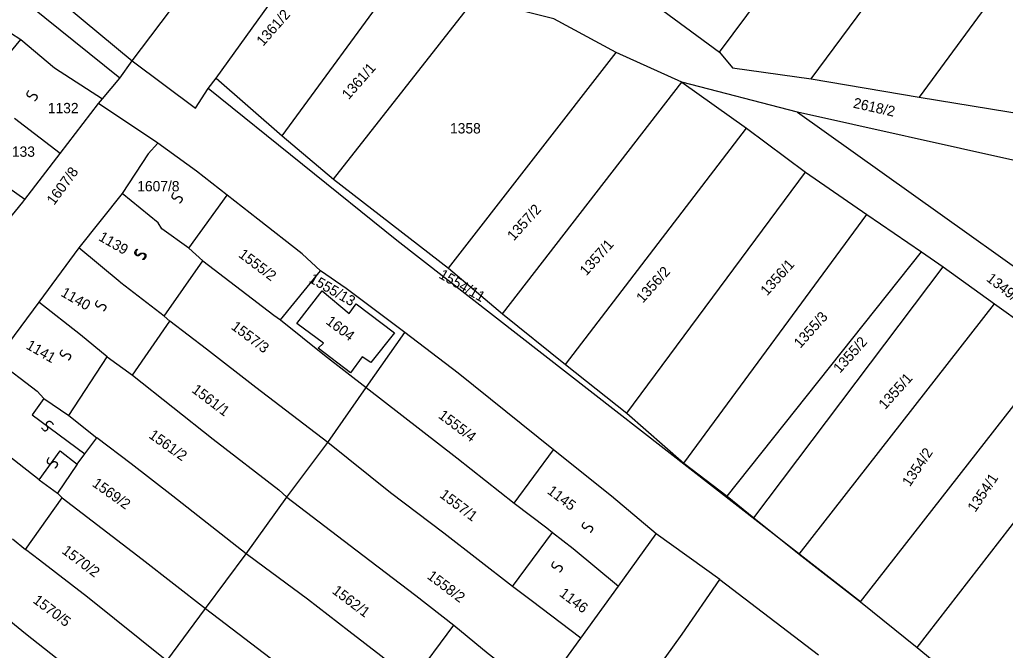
# Model space of a CAD drawing. Extents: x -581999 to -572728, y -1219553 to -1212032.
# Drawn here: x -578122.3 to -577931.4, y -1215494.4 to -1215372.3 of the extents above; entities that cross this region are included whole.
import ezdxf

# ---------------------------------------------------------------- set-up
doc = ezdxf.new("R2010")
doc.units = 0
for name, color, linetype in [('Vrstva 1', 7, 'Continuous'), ('Vrstva 2', 7, 'Continuous'), ('Vrstva 4', 7, 'Continuous'), ('Vrstva 6', 7, 'Continuous')]:
    doc.layers.add(name, color=color, linetype=linetype)

msp = doc.modelspace()

# ---------------------------------------------------------------- linework, layer by layer
at = {"layer": 'Vrstva 1'}
for p, q in [((-578100.494, -1215380.216), (-578082.103, -1215355.694)), ((-578102.918, -1215383.605), (-578100.494, -1215380.216)), ((-578049.251, -1215415.042), (-578085.815, -1215385.599)), ((-578095.516, -1215396.142), (-578107.03, -1215388.485)), ((-577959.465, -1215484.976), (-578049.251, -1215415.042)), ((-577985.234, -1215464.553), (-577947.602, -1215417.208)), ((-578071.787, -1215430.39), (-578064.022, -1215420.865)), ((-578068.651, -1215431.09), (-578063.723, -1215424.787)), ((-578063.723, -1215424.787), (-578058.496, -1215429.129)), ((-578058.496, -1215429.129), (-578057.152, -1215427.308)), ((-578057.152, -1215427.308), (-578049.686, -1215432.911)), ((-578063.424, -1215434.872), (-578068.651, -1215431.09)), ((-578049.686, -1215432.911), (-578054.315, -1215438.654)), ((-578064.47, -1215435.853), (-578063.424, -1215434.872)), ((-578058.198, -1215440.615), (-578064.47, -1215435.853)), ((-578055.958, -1215437.534), (-578058.198, -1215440.615)), ((-578054.315, -1215438.654), (-578055.958, -1215437.534)), ((-578109.693, -1215456.33), (-578107.389, -1215453.247)), ((-578111.141, -1215458.339), (-578109.693, -1215456.33)), ((-578111.141, -1215458.339), (-578114.975, -1215463.945)), ((-577986.65, -1215480.681), (-577999.043, -1215471.831))]:
    msp.add_line(p, q, dxfattribs=at)
for points in [[(-577986.724, -1215378.56), (-577942.318, -1215318.916)], [(-577968.996, -1215383.692), (-577928.473, -1215329.085)], [(-577913.954, -1215340.861), (-577948.085, -1215387.231)], [(-578106.235, -1215387.571), (-578102.918, -1215383.605), (-578123.359, -1215367.058), (-578149.788, -1215343.598)], [(-578084.26, -1215383.594), (-578067.156, -1215359.754)], [(-578071.462, -1215394.749), (-578048.947, -1215363.96)], [(-578061.488, -1215403.132), (-578034.144, -1215368.201)], [(-578006.788, -1215378.578), (-578018.826, -1215372.095), (-578034.144, -1215368.201)], [(-578113.459, -1215369.532), (-578100.494, -1215380.216), (-578088.259, -1215389.387), (-578085.815, -1215385.599), (-578084.26, -1215383.594)], [(-577999.894, -1215368.859), (-577986.724, -1215378.56)], [(-578126.151, -1215373.535), (-578122.078, -1215376.082), (-578115.59, -1215381.551)], [(-578039.247, -1215420.343), (-578006.788, -1215378.578)], [(-577994.062, -1215384.369), (-578006.788, -1215378.578)], [(-577986.724, -1215378.56), (-577984.229, -1215381.554), (-577968.996, -1215383.692)], [(-578115.59, -1215381.551), (-578106.235, -1215387.571)], [(-578084.26, -1215383.594), (-578071.462, -1215394.749)], [(-577968.996, -1215383.692), (-577948.085, -1215387.231)], [(-578028.764, -1215429.244), (-577994.062, -1215384.369)], [(-577994.062, -1215384.369), (-577981.543, -1215393.259)], [(-577971.667, -1215390.161), (-577994.062, -1215384.369)], [(-578114.476, -1215398.189), (-578107.03, -1215388.485), (-578106.235, -1215387.571)], [(-577948.085, -1215387.231), (-577923.973, -1215391.226)], [(-578114.476, -1215398.189), (-578123.285, -1215391.413)], [(-577929.364, -1215399.559), (-577971.667, -1215390.161)], [(-577971.667, -1215390.161), (-577899.516, -1215441.527), (-577893.856, -1215445.25), (-577891.34, -1215447.533), (-577869.986, -1215463.212), (-577837.934, -1215488.834)], [(-578016.564, -1215439.019), (-577981.543, -1215393.259)], [(-577981.543, -1215393.259), (-577970.066, -1215401.751)], [(-578071.462, -1215394.749), (-578061.488, -1215403.132)], [(-578088.076, -1215401.586), (-578095.516, -1215396.142), (-578097.388, -1215398.256), (-578102.479, -1215405.913)], [(-578121.289, -1215407.105), (-578114.476, -1215398.189)], [(-578121.289, -1215407.105), (-578131.743, -1215399.738)], [(-578082.13, -1215406.246), (-578088.076, -1215401.586)], [(-578004.709, -1215448.444), (-577970.066, -1215401.751)], [(-577970.066, -1215401.751), (-577958.214, -1215409.964)], [(-578061.488, -1215403.132), (-578039.247, -1215420.343)], [(-578102.479, -1215405.913), (-578110.868, -1215416.452)], [(-578095.49, -1215411.569), (-578102.479, -1215405.913)], [(-578089.544, -1215416.492), (-578082.13, -1215406.246)], [(-578047.716, -1215432.833), (-578059.067, -1215424.308), (-578064.022, -1215420.865), (-578067.607, -1215417.628), (-578076.184, -1215410.907), (-578082.13, -1215406.246)], [(-578130.278, -1215418.04), (-578121.724, -1215407.591), (-578121.289, -1215407.105)], [(-577993.632, -1215458.113), (-577958.214, -1215409.964)], [(-577958.214, -1215409.964), (-577947.602, -1215417.208), (-577943.445, -1215420.099)], [(-578094.799, -1215412.739), (-578095.49, -1215411.569)], [(-578089.544, -1215416.492), (-578094.799, -1215412.739)], [(-578110.868, -1215416.452), (-578118.619, -1215426.931)], [(-578102.732, -1215423.189), (-578102.833, -1215423.111), (-578110.868, -1215416.452)], [(-578086.832, -1215418.951), (-578089.544, -1215416.492)], [(-578094.346, -1215429.676), (-578086.832, -1215418.951)], [(-578086.832, -1215418.951), (-578073.043, -1215429.484), (-578071.787, -1215430.39), (-578063.233, -1215437.218), (-578055.191, -1215443.51)], [(-577980.066, -1215468.755), (-577943.445, -1215420.099)], [(-577943.445, -1215420.099), (-577933.487, -1215427.258)], [(-578039.247, -1215420.343), (-578028.764, -1215429.244)], [(-578094.346, -1215429.676), (-578102.732, -1215423.189)], [(-578118.619, -1215426.931), (-578126.909, -1215438.14)], [(-578110.534, -1215433.307), (-578118.619, -1215426.931)], [(-577971.31, -1215475.732), (-577933.487, -1215427.258)], [(-577933.487, -1215427.258), (-577921.22, -1215436.083)], [(-578093.249, -1215430.613), (-578094.346, -1215429.676)], [(-578028.764, -1215429.244), (-578016.564, -1215439.019)], [(-578100.437, -1215441.069), (-578093.249, -1215430.613)], [(-578062.593, -1215454.111), (-578076.594, -1215443.465), (-578086.118, -1215436.084), (-578093.249, -1215430.613)], [(-578105.338, -1215437.525), (-578110.534, -1215433.307)], [(-578055.191, -1215443.51), (-578047.716, -1215432.833)], [(-578018.91, -1215455.531), (-578037.389, -1215440.741), (-578047.716, -1215432.833)], [(-577959.465, -1215484.976), (-577921.22, -1215436.083)], [(-578126.909, -1215438.14), (-578118.938, -1215444.224)], [(-578112.759, -1215448.912), (-578105.338, -1215437.525)], [(-578105.338, -1215437.525), (-578100.437, -1215441.069)], [(-578016.564, -1215439.019), (-578004.709, -1215448.444)], [(-578100.437, -1215441.069), (-578084.807, -1215453.464), (-578072.081, -1215463.279), (-578070.581, -1215464.742)], [(-578118.938, -1215444.224), (-578117.638, -1215445.603)], [(-578062.593, -1215454.111), (-578055.191, -1215443.51)], [(-578055.191, -1215443.51), (-578037.596, -1215457.098), (-578026.496, -1215465.858)], [(-577948.48, -1215493.866), (-577910.411, -1215444.805)], [(-578117.638, -1215445.603), (-578112.759, -1215448.912)], [(-578004.709, -1215448.444), (-577993.632, -1215458.113)], [(-578112.759, -1215448.912), (-578107.389, -1215453.247)], [(-578078.452, -1215475.678), (-578092.632, -1215464.558), (-578100.714, -1215458.291), (-578107.389, -1215453.247)], [(-578070.581, -1215464.742), (-578062.593, -1215454.111)], [(-578026.822, -1215482.008), (-578040.119, -1215471.716), (-578050.479, -1215463.888), (-578062.593, -1215454.111)], [(-578118.555, -1215461.367), (-578126.341, -1215455.3), (-578126.485, -1215455.096)], [(-578026.496, -1215465.858), (-578018.91, -1215455.531)], [(-578007.667, -1215464.546), (-578018.91, -1215455.531)], [(-577993.632, -1215458.113), (-577985.234, -1215464.553), (-577980.066, -1215468.755)], [(-578118.555, -1215461.367), (-578114.975, -1215463.945)], [(-578114.975, -1215463.945), (-578114.052, -1215464.881)], [(-578121.181, -1215474.87), (-578114.052, -1215464.881)], [(-578114.052, -1215464.881), (-578098.6, -1215476.716), (-578086.334, -1215486.295)], [(-578078.452, -1215475.678), (-578070.581, -1215464.742)], [(-578070.581, -1215464.742), (-578055.814, -1215475.963), (-578045.572, -1215483.794), (-578038.19, -1215489.53)], [(-578026.496, -1215465.858), (-578020.197, -1215470.694)], [(-578006.329, -1215481.932), (-577999.043, -1215471.831), (-578007.667, -1215464.546)], [(-577980.066, -1215468.755), (-577971.31, -1215475.732)], [(-578026.822, -1215482.008), (-578019.076, -1215471.568)], [(-578020.197, -1215470.694), (-578019.076, -1215471.568)], [(-578019.076, -1215471.568), (-578015.086, -1215474.68)], [(-578123.709, -1215472.825), (-578121.181, -1215474.87)], [(-578093.797, -1215496.416), (-578109.182, -1215484.091), (-578118.478, -1215476.946), (-578121.181, -1215474.87)], [(-578015.086, -1215474.68), (-578006.329, -1215481.932)], [(-578086.334, -1215486.295), (-578078.452, -1215475.678)], [(-578046.177, -1215500.229), (-578058.565, -1215490.696), (-578066.584, -1215484.49), (-578076.432, -1215477.201), (-578078.452, -1215475.678)], [(-577971.31, -1215475.732), (-577959.465, -1215484.976)], [(-578001.754, -1215502.027), (-577993.954, -1215491.285), (-577986.65, -1215480.681), (-577967.573, -1215495.255)], [(-578131.242, -1215482.928), (-578121.147, -1215491.131), (-578108.562, -1215501.083), (-578101.378, -1215506.801)], [(-578023.246, -1215484.759), (-578026.822, -1215482.008)], [(-578013.615, -1215492.031), (-578006.329, -1215481.932)], [(-578013.615, -1215492.031), (-578023.246, -1215484.759)], [(-577959.465, -1215484.976), (-577948.48, -1215493.866)], [(-578093.797, -1215496.416), (-578086.334, -1215486.295)], [(-578086.334, -1215486.295), (-578068.619, -1215499.759), (-578054.686, -1215510.202), (-578053.533, -1215511.079)], [(-578046.177, -1215500.229), (-578038.19, -1215489.53)], [(-578038.19, -1215489.53), (-578031.56, -1215494.971), (-578021.436, -1215502.766)], [(-578020.046, -1215500.91), (-578013.615, -1215492.031)], [(-577948.48, -1215493.866), (-577926.587, -1215511.862)]]:
    msp.add_lwpolyline(points, dxfattribs=at)
at = {"layer": 'Vrstva 4'}
for p, q in [((-578130.438, -1215386.204), (-578122.078, -1215376.082)), ((-578117.638, -1215445.603), (-578119.904, -1215448.783)), ((-578119.904, -1215448.783), (-578109.693, -1215456.33)), ((-578118.555, -1215461.367), (-578114.47, -1215455.749)), ((-578114.47, -1215455.749), (-578111.141, -1215458.339))]:
    msp.add_line(p, q, dxfattribs=at)
at = {"layer": 'Vrstva 6'}
for points in [[(-578120.516, -1215385.939), (-578121.103, -1215386.561), (-578120.648, -1215387.17), (-578120.242, -1215387.158), (-578119.956, -1215386.853), (-578119.65, -1215386.699), (-578119.35, -1215386.715), (-578119.143, -1215386.817), (-578118.967, -1215387.02), (-578118.922, -1215387.384), (-578119.257, -1215387.896), (-578119.415, -1215387.988)], [(-578092.429, -1215405.741), (-578093.016, -1215406.363), (-578092.561, -1215406.972), (-578092.155, -1215406.96), (-578091.869, -1215406.655), (-578091.563, -1215406.501), (-578091.263, -1215406.517), (-578091.056, -1215406.619), (-578090.88, -1215406.822), (-578090.835, -1215407.186), (-578091.17, -1215407.698), (-578091.328, -1215407.79)], [(-578099.631, -1215416.686), (-578100.218, -1215417.308), (-578099.763, -1215417.917), (-578099.357, -1215417.905), (-578099.071, -1215417.6), (-578098.765, -1215417.446), (-578098.465, -1215417.462), (-578098.258, -1215417.564), (-578098.082, -1215417.767), (-578098.037, -1215418.131), (-578098.372, -1215418.643), (-578098.53, -1215418.735)], [(-578099.413, -1215416.686), (-578100, -1215417.308), (-578099.545, -1215417.917), (-578099.139, -1215417.905), (-578098.853, -1215417.6), (-578098.547, -1215417.446), (-578098.247, -1215417.462), (-578098.04, -1215417.564), (-578097.864, -1215417.767), (-578097.819, -1215418.131), (-578098.154, -1215418.643), (-578098.312, -1215418.735)], [(-578107.202, -1215426.634), (-578107.789, -1215427.256), (-578107.334, -1215427.865), (-578106.928, -1215427.853), (-578106.642, -1215427.548), (-578106.336, -1215427.394), (-578106.036, -1215427.41), (-578105.829, -1215427.512), (-578105.653, -1215427.715), (-578105.608, -1215428.079), (-578105.943, -1215428.591), (-578106.101, -1215428.683)], [(-578114.035, -1215436.168), (-578114.622, -1215436.79), (-578114.167, -1215437.399), (-578113.761, -1215437.387), (-578113.475, -1215437.082), (-578113.169, -1215436.928), (-578112.869, -1215436.944), (-578112.662, -1215437.046), (-578112.486, -1215437.249), (-578112.441, -1215437.613), (-578112.776, -1215438.125), (-578112.934, -1215438.217)], [(-578118.059, -1215451.288), (-578117.579, -1215451.995), (-578116.885, -1215451.684), (-578116.808, -1215451.284), (-578117.044, -1215450.939), (-578117.129, -1215450.607), (-578117.047, -1215450.317), (-578116.903, -1215450.137), (-578116.667, -1215450.009), (-578116.302, -1215450.045), (-578115.875, -1215450.484), (-578115.82, -1215450.657)], [(-578116.586, -1215457.061), (-578117.173, -1215457.683), (-578116.718, -1215458.292), (-578116.312, -1215458.28), (-578116.026, -1215457.975), (-578115.72, -1215457.821), (-578115.42, -1215457.837), (-578115.213, -1215457.939), (-578115.037, -1215458.142), (-578114.992, -1215458.506), (-578115.327, -1215459.018), (-578115.485, -1215459.11)], [(-578012.92, -1215469.538), (-578013.507, -1215470.16), (-578013.052, -1215470.769), (-578012.646, -1215470.757), (-578012.36, -1215470.452), (-578012.054, -1215470.298), (-578011.754, -1215470.314), (-578011.547, -1215470.416), (-578011.371, -1215470.619), (-578011.326, -1215470.983), (-578011.661, -1215471.495), (-578011.819, -1215471.587)], [(-578018.812, -1215477.2), (-578019.399, -1215477.822), (-578018.944, -1215478.431), (-578018.538, -1215478.419), (-578018.252, -1215478.114), (-578017.946, -1215477.96), (-578017.646, -1215477.976), (-578017.439, -1215478.078), (-578017.263, -1215478.281), (-578017.218, -1215478.645), (-578017.553, -1215479.157), (-578017.711, -1215479.249)]]:
    msp.add_open_spline(points, degree=2, dxfattribs=at)

# ---------------------------------------------------------------- texts
at = {"layer": 'Vrstva 2'}
for s, rotation, p in [('1361/2', 48.78592, (-578075.148, -1215377.504)), ('1361/1', 48.78592, (-578058.583, -1215387.855)), ('2618/2', 347.3858, (-577960.983, -1215389.268)), ('1607/8', 53.86699, (-578115.648, -1215408.315)), ('1357/2', 48.1912, (-578026.587, -1215415.199)), ('1139', 330.00851, (-578107.188, -1215414.88)), ('1357/1', 48.1912, (-578012.543, -1215421.974)), ('1555/2', 322.97209, (-578080.077, -1215418.065)), ('1356/2', 48.1912, (-578001.586, -1215427.248)), ('1356/1', 48.1912, (-577977.529, -1215425.843)), ('1555/13', 330.00851, (-578066.407, -1215422.982)), ('1554/11', 330.00851, (-578041.254, -1215422.171)), ('1349/1', 321.97007, (-577935.207, -1215422.699)), ('1140', 330.00851, (-578114.491, -1215425.66)), ('1355/3', 48.1912, (-577971.079, -1215436.004)), ('1557/3', 322.97209, (-578081.496, -1215432.022)), ('1604', 322.97209, (-578063.14, -1215431.017)), ('1141', 330.00851, (-578121.222, -1215435.851)), ('1355/2', 48.1912, (-577963.426, -1215440.849)), ('1355/1', 48.1912, (-577954.652, -1215447.88)), ('1561/1', 322.97209, (-578089.132, -1215444.266)), ('1555/4', 322.97209, (-578041.369, -1215449.234)), ('1561/2', 324.58261, (-578097.459, -1215453.098)), ('1354/2', 56.1791, (-577949.87, -1215462.836)), ('1569/2', 324.58261, (-578108.408, -1215462.458)), ('1354/1', 56.1791, (-577937.202, -1215467.779)), ('1557/1', 322.97209, (-578041.112, -1215464.605)), ('1145', 322.97209, (-578020.274, -1215463.865)), ('1570/2', 322.97209, (-578114.281, -1215475.45)), ('1558/2', 322.97209, (-578043.543, -1215480.34)), ('1562/1', 322.97209, (-578061.938, -1215483.201)), ('1146', 322.97209, (-578017.927, -1215483.718)), ('1570/5', 322.97209, (-578119.902, -1215485.023))]:
    msp.add_text(s, height=2, rotation=rotation, dxfattribs=at).set_placement(p)
for s, p in [('1132', (-578116.854, -1215390.369)), ('1358', (-578038.938, -1215394.288)), ('1133', (-578125.301, -1215398.805)), ('1607/8', (-578099.531, -1215405.498))]:
    msp.add_text(s, height=2, dxfattribs=at).set_placement(p)

doc.saveas('drawing.dxf')
